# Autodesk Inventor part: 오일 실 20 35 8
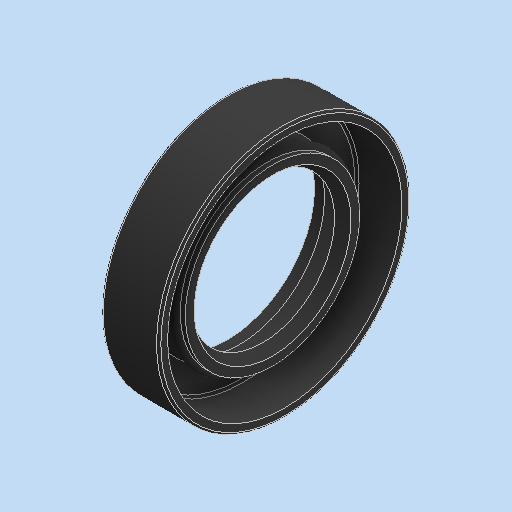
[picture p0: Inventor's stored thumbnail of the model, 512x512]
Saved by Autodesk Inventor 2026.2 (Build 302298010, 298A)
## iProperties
Created: 2026-03
Part Number: 오일 실 20 35 8
Material: 고무
Description: 오일-실
Document SubType Name: Modeling
Designer: PC-2-03
Density: 0.93 g/cm^3
Appearance: 기본값
Author: jhkim
Sending System: Autodesk Inventor 2026
Preprocessor: ST-DEVELOPER v20.1
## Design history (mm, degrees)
feature "Solid1"
node "솔리드1"
